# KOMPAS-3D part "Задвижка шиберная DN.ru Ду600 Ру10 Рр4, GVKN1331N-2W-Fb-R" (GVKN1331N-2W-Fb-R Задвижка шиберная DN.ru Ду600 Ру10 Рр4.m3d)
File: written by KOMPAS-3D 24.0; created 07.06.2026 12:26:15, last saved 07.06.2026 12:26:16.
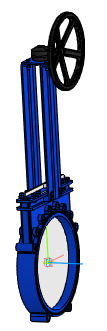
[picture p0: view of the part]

Document properties: Автор: DN.ru; Полное имя файла: E:\Работа\Зайцев\АУТСОРС\Даня\GVKN1331N-2W-Fb-R Задвижка шиберная DN.ru Ду400-600 Ру4-6\исходные материалы\DN600\DN600\GVKN1331N-2W-Fb-R Задвижка шиберная DN.ru Ду600 Ру10 Рр4.m3d

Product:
- Part/product: Задвижка шиберная DN.ru Ду600 Ру10 Рр4  | designation GVKN1331N-2W-Fb-R
    Масса: 252
    Раздел спецификации: Прочие изделия
    Примечание: D040-07325

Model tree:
1. Операция без истории:1

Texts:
  GVKN1331N-2W-Fb-R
